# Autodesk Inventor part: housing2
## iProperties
Created: 2010-11
Part Number: housing2
Document SubType Name: Modeling
Designer: ROBERT
Density: 1 g/cm^3
Author: ROBERT
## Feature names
1. Extrusion1
2. Extrusion2
3. Extrusion3
4. Extrusion4
5. Extrusion6
6. Fillet1
7. Extrusion7
8. Extrusion8
9. Extrusion9
10. Extrusion10
11. Extrusion11
12. Extrusion12
13. Extrusion13
14. Fillet2
15. Extrusion14
16. Extrusion15
17. Extrusion16
18. Extrusion17
19. Fillet3
20. Fillet4
21. TaggingFeature1
